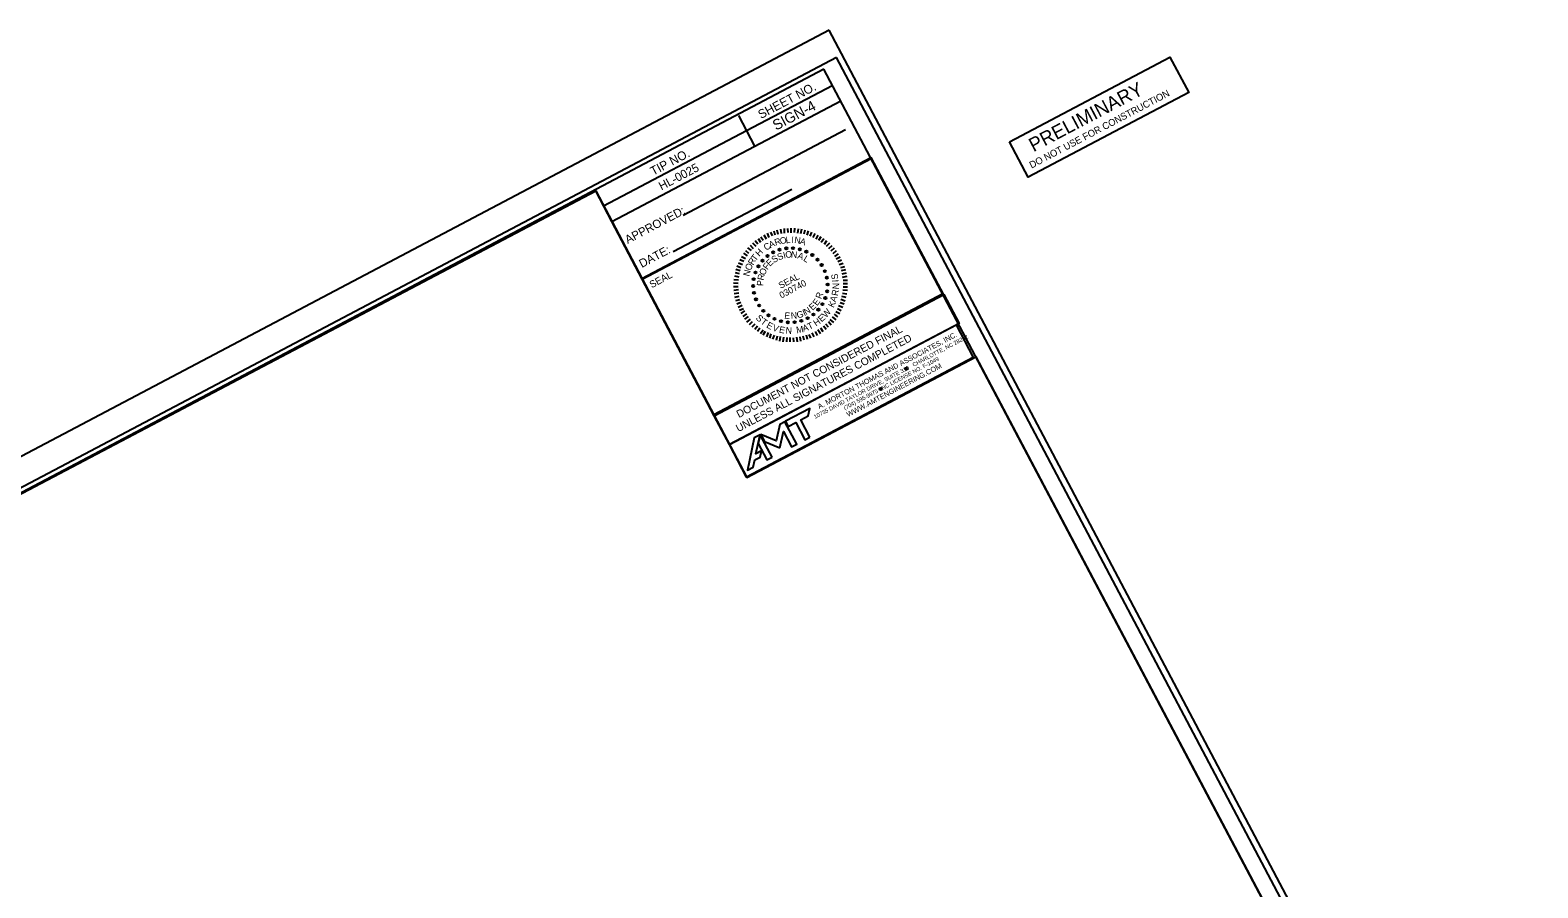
# Model space of a CAD drawing. Extents: x 1487165 to 1493546, y 497841 to 501709.
# Drawn here: x 1488254 to 1489342, y 499122 to 499742 of the extents above; entities that cross this region are included whole.
import ezdxf

# ---------------------------------------------------------------- set-up
doc = ezdxf.new("R2010")
doc.units = 0
for name, color, linetype in [('Default', 7, 'Continuous'), ('DEV PRELIMINARY STAMP CELL', 7, 'Continuous'), ('Gray Area Fill Shapes', 7, 'Continuous'), ('Old_Level_9', 7, 'Continuous'), ('Prop Grid Mask', 7, 'Continuous'), ('Prop Text', 7, 'Continuous'), ('Scratch_Level_3', 7, 'Continuous'), ('Sheet Block Title CELL', 7, 'Continuous'), ('Sheet Clip Boundary CELL', 7, 'Continuous'), ('Sheet Plan CELL', 7, 'Continuous'), ('Sheet Plot Border Inside CELL', 7, 'Continuous'), ('Sheet Plot Border Outside CELL', 7, 'Continuous'), ('Sheet Sticker Exception Certification CELL', 7, 'Continuous'), ('Sheet Title CELL', 7, 'Continuous')]:
    doc.layers.add(name, color=color, linetype=linetype)

msp = doc.modelspace()

# ---------------------------------------------------------------- linework, layer by layer
at = {"layer": 'Default'}
for p, q in [((1488827.5, 499713), (1488827.5, 499713)), ((1488827.5, 499713), (1488827.5, 499713)), ((1488827.5, 499713), (1488827.5, 499713)), ((1488827.5, 499713), (1488827.5, 499713)), ((1488827.5, 499713), (1488827.5, 499713)), ((1488827.5, 499713), (1488827.5, 499713)), ((1488827.5, 499713), (1488827.5, 499713)), ((1488827.5, 499713), (1488827.5, 499713)), ((1488777, 499658.2), (1488765.4, 499680.2)), ((1488718, 499582), (1488803.6, 499627.1))]:
    msp.add_line(p, q, dxfattribs=at)
msp.add_lwpolyline([(1488695.5, 499562.6), (1488860.8, 499649.9), (1488912.8, 499551.4), (1488747.5, 499464.1)], close=True, dxfattribs=at)
at = {"layer": 'DEV PRELIMINARY STAMP CELL'}
msp.add_lwpolyline([(1488960.8, 499661.3), (1489076.7, 499722.5), (1489090.2, 499696.9), (1488974.3, 499635.7)], close=True, dxfattribs=at)
msp.add_lwpolyline([(1488960.8, 499661.3), (1489076.7, 499722.5), (1489090.2, 499696.9), (1488974.3, 499635.7)], close=True, dxfattribs=at)
at = {"layer": 'Gray Area Fill Shapes'}
msp.add_lwpolyline([(1488960.8, 499661.3), (1489076.7, 499722.5), (1489090.2, 499696.9), (1488974.3, 499635.7)], close=True, dxfattribs=at)
at = {"layer": 'Old_Level_9'}
for p, q in [((1488790.7, 499597), (1488791.5, 499594.1)), ((1488793, 499597.7), (1488793.6, 499594.6)), ((1488795.5, 499598.1), (1488796.1, 499595.1)), ((1488798.1, 499598.7), (1488798.2, 499595.3)), ((1488800.5, 499598.8), (1488800.8, 499595.7)), ((1488802.9, 499599), (1488803, 499595.6)), ((1488805.6, 499599), (1488805.3, 499595.7)), ((1488808.2, 499598.5), (1488807.7, 499595.4)), ((1488810.6, 499598.1), (1488810, 499594.9)), ((1488813.1, 499597.6), (1488812.4, 499594.7)), ((1488815.5, 499597), (1488814.6, 499593.8)), ((1488773.6, 499586.6), (1488775.8, 499584.3)), ((1488775.3, 499588.4), (1488777.6, 499586)), ((1488777.2, 499589.9), (1488779.2, 499587.5)), ((1488779.3, 499591.5), (1488781, 499588.9)), ((1488781.4, 499592.7), (1488783.1, 499590.2)), ((1488783.6, 499594.1), (1488785.1, 499591.3)), ((1488785.9, 499595.4), (1488787.1, 499592.3)), ((1488788.2, 499596.1), (1488789.4, 499593.4)), ((1488817.9, 499596), (1488816.8, 499593.1)), ((1488820.3, 499595), (1488818.8, 499592.2)), ((1488822.5, 499593.9), (1488821, 499591.1)), ((1488824.7, 499592.6), (1488823, 499589.9)), ((1488826.8, 499591.2), (1488824.8, 499588.6)), ((1488828.7, 499589.8), (1488827, 499587.2)), ((1488830.8, 499588), (1488828.4, 499585.6)), ((1488832.6, 499586.2), (1488830.2, 499584)), ((1488766.1, 499576.3), (1488769, 499575)), ((1488767.3, 499578.4), (1488770.2, 499576.9)), ((1488768.7, 499580.9), (1488771.4, 499578.9)), ((1488770.2, 499582.8), (1488772.5, 499580.8)), ((1488771.6, 499584.7), (1488774.3, 499582.7)), ((1488834.2, 499584.4), (1488831.8, 499582.4)), ((1488835.7, 499582.5), (1488833.3, 499580.5)), ((1488837.1, 499580.3), (1488834.4, 499578.4)), ((1488838.5, 499578), (1488835.7, 499576.6)), ((1488839.6, 499575.9), (1488836.8, 499574.5)), ((1488762.4, 499564.4), (1488765.4, 499563.8)), ((1488762.7, 499566.8), (1488765.8, 499566.1)), ((1488763.4, 499569.2), (1488766.4, 499568.4)), ((1488764.1, 499571.7), (1488766.9, 499570.5)), ((1488765.1, 499574), (1488768.1, 499572.6)), ((1488840.7, 499573.5), (1488837.9, 499572.4)), ((1488841.7, 499571.1), (1488838.8, 499570.2)), ((1488842.5, 499568.8), (1488839.3, 499568.1)), ((1488843, 499566.4), (1488839.9, 499565.7)), ((1488843.5, 499563.9), (1488840.1, 499563.3)), ((1488761.7, 499559.4), (1488764.9, 499559.2)), ((1488761.7, 499556.7), (1488765, 499556.8)), ((1488761.8, 499554.2), (1488765.1, 499554.5)), ((1488761.9, 499561.8), (1488765.1, 499561.6)), ((1488843.9, 499553.9), (1488840.5, 499554.1)), ((1488843.8, 499561.2), (1488840.7, 499561.2)), ((1488843.9, 499556.2), (1488840.7, 499556.4)), ((1488843.9, 499558.8), (1488840.8, 499558.8)), ((1488762.1, 499551.7), (1488765.4, 499552.3)), ((1488762.5, 499549.2), (1488765.7, 499549.9)), ((1488763.2, 499546.6), (1488766.2, 499547.5)), ((1488764, 499544.3), (1488766.9, 499545.4)), ((1488765, 499541.9), (1488767.9, 499543.3)), ((1488840.6, 499541.5), (1488837.5, 499542.9)), ((1488841.5, 499544), (1488838.6, 499545)), ((1488842.2, 499546.2), (1488839.1, 499547.3)), ((1488842.9, 499548.8), (1488839.8, 499549.5)), ((1488843.4, 499551.3), (1488840.2, 499551.7)), ((1488766, 499539.7), (1488768.8, 499541)), ((1488767.2, 499537.4), (1488769.8, 499539.1)), ((1488768.5, 499535.2), (1488771.2, 499537.1)), ((1488769.8, 499533.2), (1488772.4, 499535.1)), ((1488771.3, 499531.1), (1488773.8, 499533.2)), ((1488773.1, 499529.4), (1488775.4, 499531.4)), ((1488832.2, 499528.9), (1488830.1, 499531.2)), ((1488834, 499530.8), (1488831.4, 499533)), ((1488835.6, 499532.8), (1488833, 499534.8)), ((1488837, 499534.8), (1488834.4, 499536.7)), ((1488838.4, 499537), (1488835.4, 499538.5)), ((1488839.4, 499539.3), (1488836.6, 499540.7)), ((1488775, 499527.7), (1488777.2, 499529.9)), ((1488777.1, 499525.9), (1488778.9, 499528.3)), ((1488778.9, 499524.5), (1488780.7, 499527)), ((1488781, 499522.9), (1488782.9, 499525.6)), ((1488783.1, 499521.8), (1488784.7, 499524.5)), ((1488785.6, 499520.5), (1488786.8, 499523.5)), ((1488787.8, 499519.5), (1488788.9, 499522.6)), ((1488790.1, 499518.7), (1488791.2, 499521.7)), ((1488792.7, 499518.1), (1488793.3, 499521.1)), ((1488795, 499517.4), (1488795.5, 499520.7)), ((1488797.5, 499516.9), (1488797.9, 499520.1)), ((1488807.7, 499516.9), (1488807.4, 499520.2)), ((1488810.2, 499517.3), (1488809.7, 499520.4)), ((1488812.7, 499518.1), (1488811.9, 499521)), ((1488815.1, 499518.6), (1488814.2, 499521.7)), ((1488817.4, 499519.4), (1488816.3, 499522.2)), ((1488819.8, 499520.4), (1488818.4, 499523.3)), ((1488822.2, 499521.5), (1488820.8, 499524.3)), ((1488824.3, 499522.7), (1488822.5, 499525.5)), ((1488826.4, 499524.1), (1488824.6, 499526.6)), ((1488828.5, 499525.7), (1488826.5, 499528.1)), ((1488830.3, 499527.3), (1488828.2, 499529.6)), ((1488800.1, 499516.8), (1488800.3, 499520)), ((1488802.6, 499516.7), (1488802.6, 499519.9)), ((1488805.1, 499516.7), (1488805, 499519.8))]:
    msp.add_line(p, q, dxfattribs=at)
for centre in [(1488782.5, 499575.4), (1488786.1, 499578.8), (1488790.2, 499581.5), (1488794.8, 499583.4), (1488799.7, 499584.4), (1488804.6, 499584.5), (1488809.5, 499583.7), (1488814.2, 499582), (1488818.5, 499579.5), (1488822.2, 499576.2), (1488777.5, 499566.9), (1488779.6, 499571.4), (1488825.2, 499572.3), (1488827.5, 499567.9), (1488829, 499563.2), (1488775.8, 499557.2), (1488776.2, 499562.1), (1488776.4, 499552.2), (1488829.2, 499553.3), (1488829.6, 499558.2), (1488777.8, 499547.5), (1488780.1, 499543.1), (1488825.8, 499544), (1488827.9, 499548.5), (1488783.2, 499539.2), (1488786.9, 499536), (1488791.2, 499533.4), (1488795.9, 499531.7), (1488800.8, 499530.9), (1488805.7, 499531), (1488810.6, 499532), (1488815.1, 499533.9), (1488819.3, 499536.6), (1488822.9, 499540)]:
    msp.add_circle(centre, 0.788, dxfattribs=at)
at = {"layer": 'Prop Grid Mask'}
msp.add_lwpolyline([(1488758.7, 499442.6), (1488922.3, 499529), (1488934.7, 499505.5), (1488771.1, 499419.1)], close=True, dxfattribs=at)
at = {"layer": 'Prop Text'}
msp.add_line((1488725.2, 499608.3), (1488842.5, 499670.2), dxfattribs=at)
at = {"layer": 'Scratch_Level_3'}
msp.add_lwpolyline([(1487512.6, 499019.7), (1488662.1, 499625.8), (1488771.2, 499418.9), (1488936.6, 499506), (1489317.2, 498785.2), (1488242.7, 498217.8), (1488120.4, 498369.2), (1487949.5, 498194.2)], close=True, dxfattribs=at)
at = {"layer": 'Sheet Block Title CELL'}
for p, q in [((1488771.1, 499669.4), (1488833.2, 499702.2)), ((1488673.7, 499603.7), (1488839.1, 499690.9)), ((1488777, 499658.2), (1488765.4, 499680.2)), ((1488667.8, 499615), (1488771.1, 499669.4)), ((1488673.7, 499603.7), (1488662.1, 499625.8)), ((1488695.7, 499562), (1488673.7, 499603.7))]:
    msp.add_line(p, q, dxfattribs=at)
for points in [[(1488826.9, 499713.7), (1487500.5, 499013.3), (1487990.8, 498084.8), (1489317.2, 498785.2)], [(1488695.7, 499562), (1488861.1, 499649.2), (1488913.1, 499550.7), (1488747.7, 499463.4)], [(1488758.7, 499442.6), (1488922.3, 499529), (1488934.7, 499505.5), (1488771.1, 499419.1)]]:
    msp.add_lwpolyline(points, close=True, dxfattribs=at)
for points in [[(1488816.8, 499448), (1488810.3, 499460.5), (1488815.6, 499463.3), (1488816.8, 499468.7), (1488799.2, 499459.4), (1488801.1, 499455.6), (1488806.5, 499458.5), (1488813.1, 499446), (1488816.8, 499448)], [(1488795.1, 499440.2), (1488797.7, 499452), (1488803.5, 499441), (1488807.2, 499442.9), (1488798.7, 499459.1), (1488795, 499457.1), (1488792.4, 499445.4), (1488781.3, 499449.9), (1488784, 499444.8), (1488795.1, 499440.2)], [(1488779.4, 499443.4), (1488780.8, 499449.7), (1488776.5, 499447.4), (1488771.6, 499424.1), (1488775.8, 499426.3), (1488776.9, 499431.6), (1488780.8, 499433.6), (1488781.8, 499438), (1488777.8, 499435.9), (1488779.4, 499443.4)], [(1488789.4, 499433.5), (1488780.8, 499449.7), (1488779.4, 499443.4), (1488785.7, 499431.5), (1488789.4, 499433.5)]]:
    msp.add_lwpolyline(points, dxfattribs=at)
for centre in [(1488886.4, 499497.4), (1488867.9, 499482.7)]:
    msp.add_circle(centre, 0.833, dxfattribs=at)
at = {"layer": 'Sheet Clip Boundary CELL'}
msp.add_lwpolyline([(1487500.5, 499013.2), (1488662.1, 499625.8), (1488771.2, 499418.9), (1488936.6, 499506), (1489317.2, 498785.1), (1487990.8, 498084.7)], close=True, dxfattribs=at)
at = {"layer": 'Sheet Plan CELL'}
for p, q in [((1488830.6, 499742), (1488830.6, 499742)), ((1488835.9, 499722.2), (1488835.9, 499722.2))]:
    msp.add_line(p, q, dxfattribs=at)
at = {"layer": 'Sheet Plot Border Inside CELL'}
msp.add_lwpolyline([(1488835.9, 499722.2), (1487363.2, 498944.6), (1487856.2, 498010.8), (1489329, 498788.5)], close=True, dxfattribs=at)
at = {"layer": 'Sheet Plot Border Outside CELL'}
msp.add_lwpolyline([(1488830.6, 499742), (1487342.4, 498956.2), (1487854.1, 497987.1), (1489342.3, 498772.9)], close=True, dxfattribs=at)
at = {"layer": 'Sheet Sticker Exception Certification CELL'}
msp.add_lwpolyline([(1488747.7, 499463.4), (1488913.5, 499550.9), (1488924.5, 499530.1), (1488758.7, 499442.6)], close=True, dxfattribs=at)
at = {"layer": 'Sheet Title CELL'}
msp.add_line((1488912.9, 499551.3), (1488747.5, 499464.1), dxfattribs=at)

# ---------------------------------------------------------------- texts
at = {"layer": 'DEV PRELIMINARY STAMP CELL'}
for s, height, p in [(' PRELIMINARY', 10, (1488974.9, 499652)), ('DO NOT USE FOR CONSTRUCTION', 5, (1488976.8, 499641.9))]:
    msp.add_text(s, height=height, rotation=27.8351, dxfattribs=at).set_placement(p)
at = {"layer": 'Old_Level_9'}
for s, height, rotation, p in [('C', 4.72, 32.775, (1488785.2, 499582.5)), ('A', 4.72, 25.81, (1488788.3, 499584.4)), ('R', 4.72, 17.8566, (1488792, 499586.2)), ('O', 4.72, 10.9219, (1488795.5, 499587.3)), ('L', 4.72, 3.581, (1488799.4, 499588)), ('I', 4.72, 358.641, (1488803.4, 499588.2)), ('N', 4.72, 352.7389, (1488805.3, 499588.2)), ('A', 4.72, 344.8402, (1488809.1, 499587.5)), ('R', 4.72, 60.0105, (1488775.8, 499571.8)), ('T', 4.72, 53.2709, (1488777.6, 499574.7)), ('H', 4.72, 45.5784, (1488780.2, 499578.1)), ('E', 4.7, 44.424, (1488787.9, 499571)), ('S', 4.7, 32.3031, (1488790.8, 499573.6)), ('S', 4.7, 20.8765, (1488794.2, 499575.6)), ('I', 4.7, 13.3172, (1488798, 499577)), ('O', 4.7, 5.71, (1488799.2, 499577.4)), ('N', 4.7, 355.2281, (1488802.9, 499577.7)), ('A', 4.7, 341.7789, (1488807.4, 499577.2)), ('L', 4.7, 329.3674, (1488811.6, 499575.6)), ('N', 4.72, 75.9017, (1488773, 499563.8)), ('O', 4.72, 67.7793, (1488774, 499567.9)), ('R', 4.7, 77.5829, (1488783.3, 499560.9)), ('O', 4.7, 66.0869, (1488784.1, 499564.4)), ('F', 4.7, 54.235, (1488786.1, 499568.5)), ('SEAL', 4.7, 27.8351, (1488795.6, 499555)), ('S', 4.72, 100.093, (1488837.4, 499562.3)), ('P', 4.7, 87.9587, (1488783.1, 499557.1)), ('030740', 4.7, 27.8351, (1488796.2, 499548)), ('R', 4.72, 78.9854, (1488836.9, 499549.7)), ('I', 4.72, 93.8815, (1488837.6, 499560.1)), ('N', 4.72, 87.2077, (1488837.7, 499554.7)), ('N', 4.7, 30.9629, (1488814, 499536)), ('E', 4.7, 43.6408, (1488818.7, 499539.2)), ('E', 4.7, 54.9919, (1488822.1, 499542.5)), ('R', 4.7, 68.1844, (1488824.9, 499547.4)), ('K', 4.72, 63.9761, (1488833.8, 499541.1)), ('A', 4.72, 71.3568, (1488835.4, 499545.1)), ('S', 4.72, 316.0471, (1488777.3, 499533.6)), ('T', 4.72, 323.4595, (1488780.7, 499530.4)), ('E', 4.72, 331.6576, (1488784.9, 499527.4)), ('E', 4.7, 352.7043, (1488798.1, 499533.7)), ('N', 4.7, 3.8935, (1488803.1, 499533.4)), ('G', 4.7, 15.3163, (1488807.9, 499533.7)), ('I', 4.7, 23.4597, (1488812.7, 499535.3)), ('T', 4.72, 25.2217, (1488816.3, 499525.4)), ('H', 4.72, 33.8463, (1488821.2, 499527.8)), ('E', 4.72, 41.9998, (1488825.2, 499530.8)), ('W', 4.72, 49.8409, (1488828.5, 499533.8)), ('V', 4.72, 339.7649, (1488789.3, 499525.2)), ('E', 4.72, 348.0663, (1488794.2, 499523.6)), ('N', 4.72, 356.1641, (1488799.1, 499522.8)), ('M', 4.72, 10.1721, (1488807.3, 499522.9)), ('A', 4.72, 18.0173, (1488812.2, 499524))]:
    msp.add_text(s, height=height, rotation=rotation, dxfattribs=at).set_placement(p)
at = {"layer": 'Prop Text'}
for s, height, p in [('SHEET NO.', 6.36, (1488781.4, 499677.7)), ('TIP NO.', 6.36, (1488703.6, 499636.7)), ('HL-0025', 6.11, (1488709.6, 499626.1)), ('APPROVED:', 6.11, (1488685.2, 499587.5)), ('DATE:', 6.11, (1488695.4, 499570.1)), ('SEAL', 5.09, (1488702.6, 499555.5))]:
    msp.add_text(s, height=height, rotation=27.7992, dxfattribs=at).set_placement(p)
at = {"layer": 'Sheet Block Title CELL'}
for s, height, p in [('A. MORTON THOMAS AND ASSOCIATES, INC.', 3.75, (1488823.5, 499468.1)), ('10735 DAVID TAYLOR DRIVE, SUITE 310   CHARLOTTE, NC 28262', 2.917, (1488820.5, 499461.1)), ('(704) 595-9975   NC LICENSE NO. F-1049', 2.917, (1488842, 499467.5)), ('WWW.AMTENGINEERING.COM', 3.75, (1488844.4, 499462.4))]:
    msp.add_text(s, height=height, rotation=27.8346, dxfattribs=at).set_placement(p)
at = {"layer": 'Sheet Sticker Exception Certification CELL'}
for s, p in [('UNLESS ALL SIGNATURES COMPLETED', (1488765.1, 499451.5)), ('DOCUMENT NOT CONSIDERED FINAL', (1488765.5, 499461.7))]:
    msp.add_text(s, height=5.5, rotation=27.8043, dxfattribs=at).set_placement(p)
at = {"layer": 'Sheet Title CELL'}
msp.add_text('SIGN-4', height=7.5, rotation=27.8034, dxfattribs=at).set_placement((1488792.3, 499669.3))

doc.saveas('drawing.dxf')
